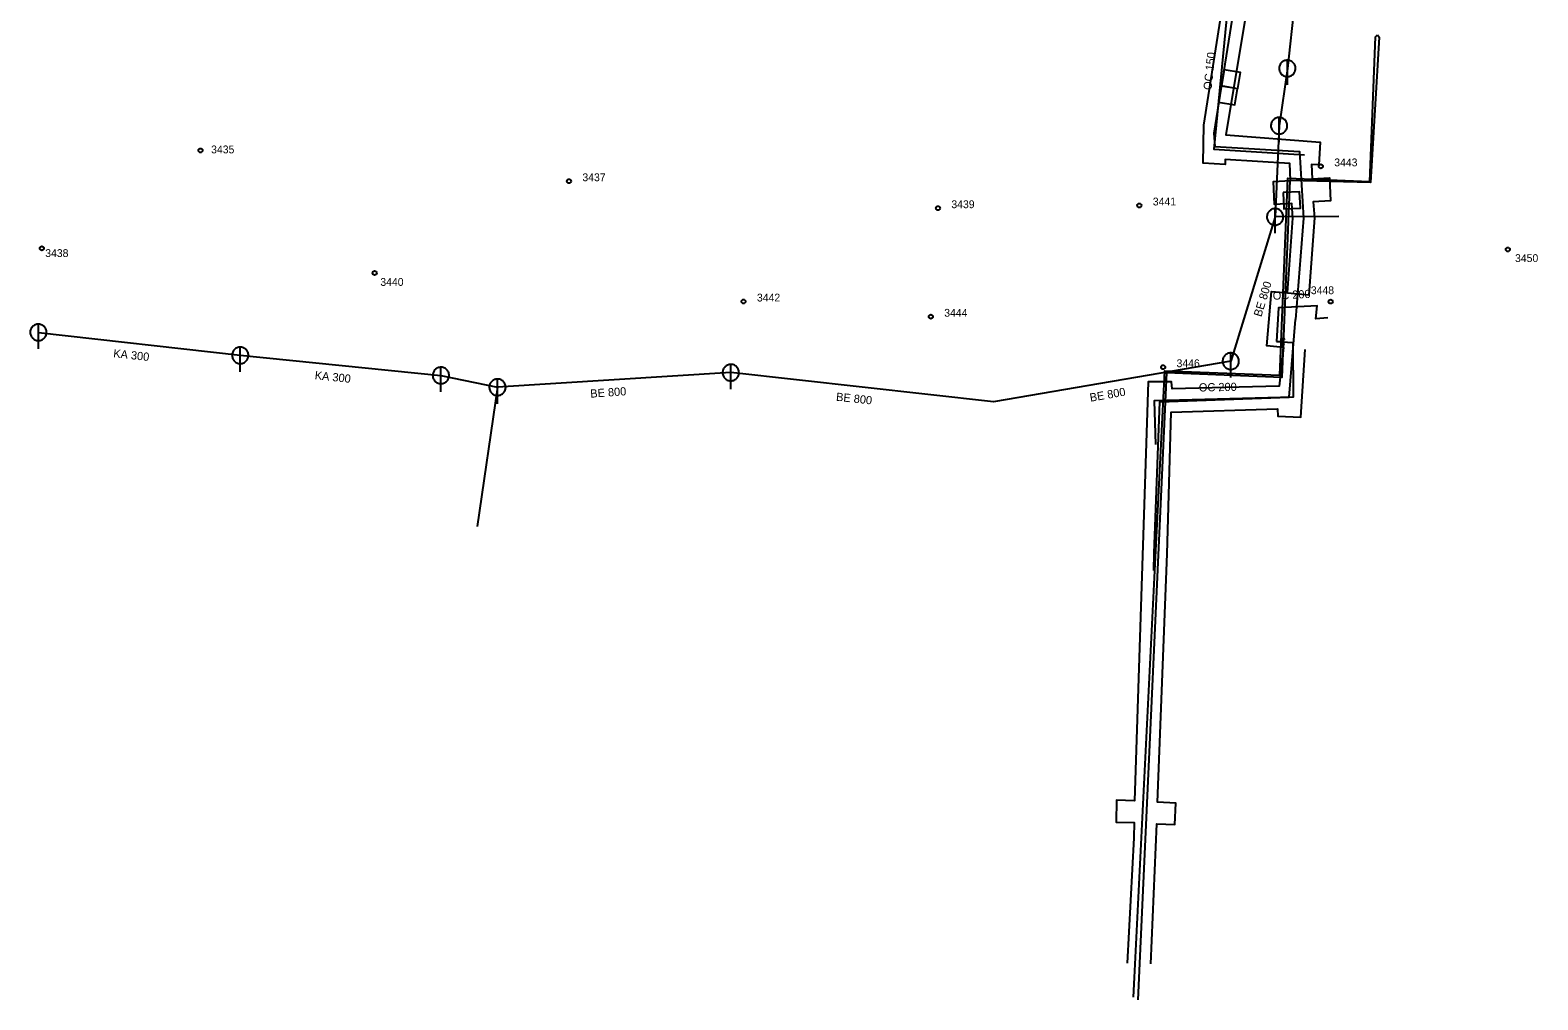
# Model space of a CAD drawing. Extents: x -759784 to -759434, y -974861 to -974639.
# Drawn here: x -759617.7 to -759434.2, y -974860.7 to -974742.8 of the extents above; entities that cross this region are included whole.
import ezdxf

# ---------------------------------------------------------------- set-up
doc = ezdxf.new("R2010")
doc.units = 0
for name, color, linetype in [('IS_CETIN_kolektor', 7, 'Continuous'), ('IS_CETIN_sdělovací kabel_podzemní', 7, 'Continuous'), ('IS_CEZ_Teplarenská_horkovod', 7, 'Continuous'), ('IS_CEZ_Teplarenská_kondenzát', 7, 'Continuous'), ('IS_DpmUL_stožáry', 7, 'Continuous'), ('IS_popis_DpmUL', 7, 'Continuous'), ('IS_popis_ScVK', 7, 'Continuous'), ('IS_ScVK_Kanal', 7, 'Continuous'), ('IS_ScVK_Vodovod', 7, 'Continuous')]:
    doc.layers.add(name, color=color, linetype=linetype)

msp = doc.modelspace()

# ---------------------------------------------------------------- linework, layer by layer
at = {"layer": 'IS_CETIN_kolektor'}
for points in [[(-759464.71, -974774.76), (-759464.04, -974765.67), (-759464.19, -974763.9), (-759466.29, -974764), (-759466.42, -974761.21), (-759464.33, -974761.1), (-759464.43, -974759.03), (-759472.28, -974758.54), (-759472.29, -974759.14), (-759474.98, -974758.97), (-759474.9, -974754.36), (-759472.4, -974738.58)], [(-759469.43, -974738.93), (-759472.22, -974755.53), (-759460.73, -974756.42), (-759460.88, -974759.18), (-759461.79, -974759.14), (-759461.7, -974760.88), (-759459.6, -974760.78), (-759459.47, -974763.57), (-759461.56, -974763.68), (-759461.4, -974765.63), (-759462.09, -974774.99)], [(-759465.2, -974781.4), (-759467.22, -974781.22), (-759466.64, -974774.59), (-759464.71, -974774.76)], [(-759464.71, -974774.76), (-759462.09, -974774.99)], [(-759465.2, -974781.4), (-759465.72, -974786.1), (-759478.75, -974786.43), (-759478.8, -974785.59), (-759481.66, -974785.6), (-759483.33, -974836.55), (-759485.53, -974836.45), (-759485.57, -974839.15), (-759483.37, -974839.19), (-759483.4, -974841.03), (-759484.22, -974856.27)], [(-759481.35, -974856.37), (-759480.62, -974839.33), (-759478.42, -974839.42), (-759478.31, -974836.81), (-759480.51, -974836.71), (-759479.35, -974806.49), (-759478.84, -974789.28), (-759465.9, -974788.85), (-759465.86, -974789.74), (-759463.08, -974789.88), (-759462.57, -974781.63)]]:
    msp.add_lwpolyline(points, dxfattribs=at)
for points in [[(-759472.39, -974747.62), (-759472.722, -974749.593), (-759470.749, -974749.924), (-759470.417, -974747.952)], [(-759472.76, -974749.6), (-759473.092, -974751.573), (-759471.119, -974751.904), (-759470.787, -974749.932)], [(-759465.23, -974762.56), (-759465.137, -974764.558), (-759463.139, -974764.465), (-759463.232, -974762.467)]]:
    msp.add_lwpolyline(points, close=True, dxfattribs=at)
at = {"layer": 'IS_CETIN_sdělovací kabel_podzemní'}
for points in [[(-759454.97, -974692.92), (-759455.48, -974700.73), (-759455.96, -974712.17), (-759466.21, -974711.58), (-759468.57, -974724.36), (-759470.97, -974738.53), (-759473.67, -974755.35), (-759473.56, -974756.95), (-759463.26, -974757.59), (-759462.76, -974765.66), (-759463.72, -974777.99)], [(-759480.98, -974808.53), (-759480.91, -974806.42), (-759480.24, -974788), (-759464.48, -974787.46), (-759463.72, -974777.99)]]:
    msp.add_lwpolyline(points, dxfattribs=at)
at = {"layer": 'IS_CEZ_Teplarenská_horkovod'}
msp.add_lwpolyline([(-759483.46, -974860.4), (-759483.34, -974858.04), (-759479.64, -974784.23), (-759465.65, -974784.79), (-759464.68, -974760.81), (-759454.69, -974761.21), (-759454, -974743.63), (-759453.75, -974743.37)], dxfattribs=at)
at = {"layer": 'IS_CEZ_Teplarenská_kondenzát'}
msp.add_lwpolyline([(-759453.75, -974743.37), (-759453.55, -974743.65), (-759454.59, -974761.34), (-759464.4, -974761.09), (-759465.39, -974785.05), (-759479.43, -974784.47), (-759482.91, -974860.74)], dxfattribs=at)
at = {"layer": 'IS_DpmUL_stožáry'}
for centre in [(-759596.978, -974757.443), (-759460.648, -974759.373), (-759552.138, -974761.183), (-759482.728, -974764.133), (-759507.238, -974764.463), (-759616.288, -974769.343), (-759437.888, -974769.483), (-759575.788, -974772.343), (-759530.898, -974775.813), (-759459.448, -974775.823), (-759508.108, -974777.663), (-759479.838, -974783.803)]:
    msp.add_circle(centre, 0.25, dxfattribs=at)
at = {"layer": 'IS_ScVK_Kanal'}
for points in [[(-759462.129, -974723.827), (-759464.723, -974747.469)], [(-759464.723, -974747.469), (-759465.724, -974754.43)], [(-759463.723, -974747.469), (-759463.728, -974747.36), (-759463.746, -974747.252), (-759463.776, -974747.146), (-759463.816, -974747.045), (-759463.868, -974746.948), (-759463.93, -974746.858), (-759464.002, -974746.775), (-759464.082, -974746.701), (-759464.17, -974746.635), (-759464.264, -974746.58), (-759464.364, -974746.535), (-759464.469, -974746.502), (-759464.576, -974746.48), (-759464.685, -974746.47), (-759464.795, -974746.472), (-759464.903, -974746.486), (-759465.01, -974746.511), (-759465.113, -974746.548), (-759465.211, -974746.597), (-759465.303, -974746.655), (-759465.389, -974746.724), (-759465.466, -974746.801), (-759465.535, -974746.887), (-759465.594, -974746.979), (-759465.642, -974747.077), (-759465.679, -974747.18), (-759465.705, -974747.287), (-759465.719, -974747.395), (-759465.722, -974747.505), (-759465.712, -974747.614), (-759465.691, -974747.721), (-759465.657, -974747.825), (-759465.613, -974747.925), (-759465.558, -974748.02), (-759465.492, -974748.108), (-759465.418, -974748.188), (-759465.335, -974748.26), (-759465.245, -974748.322), (-759465.149, -974748.374), (-759465.047, -974748.415), (-759464.942, -974748.445), (-759464.834, -974748.463), (-759464.724, -974748.469), (-759464.615, -974748.463), (-759464.507, -974748.445), (-759464.402, -974748.416), (-759464.3, -974748.375), (-759464.203, -974748.323), (-759464.113, -974748.261), (-759464.03, -974748.19), (-759463.955, -974748.11), (-759463.89, -974748.022), (-759463.834, -974747.928), (-759463.79, -974747.828), (-759463.756, -974747.724), (-759463.734, -974747.616), (-759463.724, -974747.507), (-759463.723, -974747.469)], [(-759464.723, -974749.469), (-759464.722, -974746.469)], [(-759464.724, -974754.43), (-759464.729, -974754.321), (-759464.747, -974754.213), (-759464.777, -974754.107), (-759464.817, -974754.006), (-759464.869, -974753.909), (-759464.931, -974753.819), (-759465.003, -974753.736), (-759465.083, -974753.662), (-759465.171, -974753.596), (-759465.265, -974753.541), (-759465.365, -974753.496), (-759465.47, -974753.463), (-759465.577, -974753.441), (-759465.686, -974753.431), (-759465.796, -974753.433), (-759465.904, -974753.447), (-759466.011, -974753.472), (-759466.114, -974753.509), (-759466.212, -974753.558), (-759466.304, -974753.616), (-759466.39, -974753.685), (-759466.467, -974753.762), (-759466.536, -974753.848), (-759466.595, -974753.94), (-759466.643, -974754.038), (-759466.68, -974754.141), (-759466.706, -974754.248), (-759466.72, -974754.356), (-759466.723, -974754.466), (-759466.713, -974754.575), (-759466.692, -974754.682), (-759466.658, -974754.786), (-759466.614, -974754.886), (-759466.559, -974754.981), (-759466.493, -974755.069), (-759466.419, -974755.149), (-759466.336, -974755.221), (-759466.246, -974755.283), (-759466.15, -974755.335), (-759466.048, -974755.376), (-759465.943, -974755.406), (-759465.835, -974755.424), (-759465.725, -974755.43), (-759465.616, -974755.424), (-759465.508, -974755.406), (-759465.403, -974755.377), (-759465.301, -974755.336), (-759465.204, -974755.284), (-759465.114, -974755.222), (-759465.031, -974755.151), (-759464.956, -974755.071), (-759464.891, -974754.983), (-759464.835, -974754.889), (-759464.791, -974754.789), (-759464.757, -974754.685), (-759464.735, -974754.577), (-759464.725, -974754.468), (-759464.724, -974754.43)], [(-759465.724, -974754.43), (-759466.209, -974765.517)], [(-759465.724, -974756.43), (-759465.723, -974753.43)], [(-759466.209, -974765.517), (-759471.607, -974783.071)], [(-759465.209, -974765.517), (-759465.214, -974765.408), (-759465.232, -974765.3), (-759465.262, -974765.194), (-759465.302, -974765.093), (-759465.354, -974764.996), (-759465.416, -974764.906), (-759465.488, -974764.823), (-759465.568, -974764.749), (-759465.656, -974764.683), (-759465.75, -974764.628), (-759465.85, -974764.583), (-759465.955, -974764.55), (-759466.062, -974764.528), (-759466.171, -974764.518), (-759466.281, -974764.52), (-759466.389, -974764.534), (-759466.496, -974764.559), (-759466.599, -974764.596), (-759466.697, -974764.645), (-759466.789, -974764.703), (-759466.875, -974764.772), (-759466.952, -974764.849), (-759467.021, -974764.935), (-759467.08, -974765.027), (-759467.128, -974765.125), (-759467.165, -974765.228), (-759467.191, -974765.335), (-759467.205, -974765.443), (-759467.208, -974765.553), (-759467.198, -974765.662), (-759467.177, -974765.769), (-759467.143, -974765.873), (-759467.099, -974765.973), (-759467.044, -974766.068), (-759466.978, -974766.156), (-759466.904, -974766.236), (-759466.821, -974766.308), (-759466.731, -974766.37), (-759466.635, -974766.422), (-759466.533, -974766.463), (-759466.428, -974766.493), (-759466.32, -974766.511), (-759466.21, -974766.517), (-759466.101, -974766.511), (-759465.993, -974766.493), (-759465.888, -974766.464), (-759465.786, -974766.423), (-759465.689, -974766.371), (-759465.599, -974766.309), (-759465.516, -974766.238), (-759465.441, -974766.158), (-759465.376, -974766.07), (-759465.32, -974765.976), (-759465.276, -974765.876), (-759465.242, -974765.772), (-759465.22, -974765.664), (-759465.21, -974765.555), (-759465.209, -974765.517)], [(-759466.209, -974767.517), (-759466.208, -974764.517)], [(-759458.451, -974765.485), (-759466.209, -974765.517)], [(-759615.708, -974779.566), (-759615.713, -974779.457), (-759615.731, -974779.349), (-759615.761, -974779.243), (-759615.801, -974779.142), (-759615.853, -974779.045), (-759615.915, -974778.955), (-759615.987, -974778.872), (-759616.067, -974778.798), (-759616.155, -974778.732), (-759616.249, -974778.677), (-759616.349, -974778.632), (-759616.454, -974778.599), (-759616.561, -974778.577), (-759616.67, -974778.567), (-759616.78, -974778.569), (-759616.888, -974778.583), (-759616.995, -974778.608), (-759617.098, -974778.645), (-759617.196, -974778.694), (-759617.288, -974778.752), (-759617.374, -974778.821), (-759617.451, -974778.898), (-759617.52, -974778.984), (-759617.579, -974779.076), (-759617.627, -974779.174), (-759617.664, -974779.277), (-759617.69, -974779.384), (-759617.704, -974779.492), (-759617.707, -974779.602), (-759617.697, -974779.711), (-759617.676, -974779.818), (-759617.642, -974779.922), (-759617.598, -974780.022), (-759617.543, -974780.117), (-759617.477, -974780.205), (-759617.403, -974780.285), (-759617.32, -974780.357), (-759617.23, -974780.419), (-759617.134, -974780.471), (-759617.032, -974780.512), (-759616.927, -974780.542), (-759616.819, -974780.56), (-759616.709, -974780.566), (-759616.6, -974780.56), (-759616.492, -974780.542), (-759616.387, -974780.513), (-759616.285, -974780.472), (-759616.188, -974780.42), (-759616.098, -974780.358), (-759616.015, -974780.287), (-759615.94, -974780.207), (-759615.875, -974780.119), (-759615.819, -974780.025), (-759615.775, -974779.925), (-759615.741, -974779.821), (-759615.719, -974779.713), (-759615.709, -974779.604), (-759615.708, -974779.566)], [(-759616.708, -974781.566), (-759616.707, -974778.566)], [(-759616.708, -974779.566), (-759592.136, -974782.359)], [(-759591.136, -974782.359), (-759591.141, -974782.25), (-759591.159, -974782.142), (-759591.189, -974782.036), (-759591.229, -974781.935), (-759591.281, -974781.838), (-759591.343, -974781.748), (-759591.415, -974781.665), (-759591.495, -974781.591), (-759591.583, -974781.525), (-759591.677, -974781.47), (-759591.777, -974781.425), (-759591.882, -974781.392), (-759591.989, -974781.37), (-759592.098, -974781.36), (-759592.208, -974781.362), (-759592.316, -974781.376), (-759592.423, -974781.401), (-759592.526, -974781.438), (-759592.624, -974781.487), (-759592.716, -974781.545), (-759592.802, -974781.614), (-759592.879, -974781.691), (-759592.948, -974781.777), (-759593.007, -974781.869), (-759593.055, -974781.967), (-759593.092, -974782.07), (-759593.118, -974782.177), (-759593.132, -974782.285), (-759593.135, -974782.395), (-759593.125, -974782.504), (-759593.104, -974782.611), (-759593.07, -974782.715), (-759593.026, -974782.815), (-759592.971, -974782.91), (-759592.905, -974782.998), (-759592.831, -974783.078), (-759592.748, -974783.15), (-759592.658, -974783.212), (-759592.562, -974783.264), (-759592.46, -974783.305), (-759592.355, -974783.335), (-759592.247, -974783.353), (-759592.137, -974783.359), (-759592.028, -974783.353), (-759591.92, -974783.335), (-759591.815, -974783.306), (-759591.713, -974783.265), (-759591.616, -974783.213), (-759591.526, -974783.151), (-759591.443, -974783.08), (-759591.368, -974783), (-759591.303, -974782.912), (-759591.247, -974782.818), (-759591.203, -974782.718), (-759591.169, -974782.614), (-759591.147, -974782.506), (-759591.137, -974782.397), (-759591.136, -974782.359)], [(-759592.136, -974784.359), (-759592.135, -974781.359)], [(-759592.136, -974782.359), (-759567.72, -974784.807)], [(-759470.607, -974783.071), (-759470.612, -974782.962), (-759470.63, -974782.854), (-759470.66, -974782.748), (-759470.7, -974782.647), (-759470.752, -974782.55), (-759470.814, -974782.46), (-759470.886, -974782.377), (-759470.966, -974782.303), (-759471.054, -974782.237), (-759471.148, -974782.182), (-759471.248, -974782.137), (-759471.353, -974782.104), (-759471.46, -974782.082), (-759471.569, -974782.072), (-759471.679, -974782.074), (-759471.787, -974782.088), (-759471.894, -974782.113), (-759471.997, -974782.15), (-759472.095, -974782.199), (-759472.187, -974782.257), (-759472.273, -974782.326), (-759472.35, -974782.403), (-759472.419, -974782.489), (-759472.478, -974782.581), (-759472.526, -974782.679), (-759472.563, -974782.782), (-759472.589, -974782.889), (-759472.603, -974782.997), (-759472.606, -974783.107), (-759472.596, -974783.216), (-759472.575, -974783.323), (-759472.541, -974783.427), (-759472.497, -974783.527), (-759472.442, -974783.622), (-759472.376, -974783.71), (-759472.302, -974783.79), (-759472.219, -974783.862), (-759472.129, -974783.924), (-759472.033, -974783.976), (-759471.931, -974784.017), (-759471.826, -974784.047), (-759471.718, -974784.065), (-759471.608, -974784.071), (-759471.499, -974784.065), (-759471.391, -974784.047), (-759471.286, -974784.018), (-759471.184, -974783.977), (-759471.087, -974783.925), (-759470.997, -974783.863), (-759470.914, -974783.792), (-759470.839, -974783.712), (-759470.774, -974783.624), (-759470.718, -974783.53), (-759470.674, -974783.43), (-759470.64, -974783.326), (-759470.618, -974783.218), (-759470.608, -974783.109), (-759470.607, -974783.071)], [(-759471.607, -974785.071), (-759471.606, -974782.071)], [(-759566.72, -974784.807), (-759566.725, -974784.698), (-759566.743, -974784.59), (-759566.773, -974784.484), (-759566.813, -974784.383), (-759566.865, -974784.286), (-759566.927, -974784.196), (-759566.999, -974784.113), (-759567.079, -974784.039), (-759567.167, -974783.973), (-759567.261, -974783.918), (-759567.361, -974783.873), (-759567.466, -974783.84), (-759567.573, -974783.818), (-759567.682, -974783.808), (-759567.792, -974783.81), (-759567.9, -974783.824), (-759568.007, -974783.849), (-759568.11, -974783.886), (-759568.208, -974783.935), (-759568.3, -974783.993), (-759568.386, -974784.062), (-759568.463, -974784.139), (-759568.532, -974784.225), (-759568.591, -974784.317), (-759568.639, -974784.415), (-759568.676, -974784.518), (-759568.702, -974784.625), (-759568.716, -974784.733), (-759568.719, -974784.843), (-759568.709, -974784.952), (-759568.688, -974785.059), (-759568.654, -974785.163), (-759568.61, -974785.263), (-759568.555, -974785.358), (-759568.489, -974785.446), (-759568.415, -974785.526), (-759568.332, -974785.598), (-759568.242, -974785.66), (-759568.146, -974785.712), (-759568.044, -974785.753), (-759567.939, -974785.783), (-759567.831, -974785.801), (-759567.721, -974785.807), (-759567.612, -974785.801), (-759567.504, -974785.783), (-759567.399, -974785.754), (-759567.297, -974785.713), (-759567.2, -974785.661), (-759567.11, -974785.599), (-759567.027, -974785.528), (-759566.952, -974785.448), (-759566.887, -974785.36), (-759566.831, -974785.266), (-759566.787, -974785.166), (-759566.753, -974785.062), (-759566.731, -974784.954), (-759566.721, -974784.845), (-759566.72, -974784.807)], [(-759567.72, -974786.807), (-759567.719, -974783.807)], [(-759531.449, -974784.457), (-759531.454, -974784.348), (-759531.472, -974784.24), (-759531.502, -974784.134), (-759531.542, -974784.033), (-759531.594, -974783.936), (-759531.656, -974783.846), (-759531.728, -974783.763), (-759531.808, -974783.689), (-759531.896, -974783.623), (-759531.99, -974783.568), (-759532.09, -974783.523), (-759532.195, -974783.49), (-759532.302, -974783.468), (-759532.411, -974783.458), (-759532.521, -974783.46), (-759532.629, -974783.474), (-759532.736, -974783.499), (-759532.839, -974783.536), (-759532.937, -974783.585), (-759533.029, -974783.643), (-759533.115, -974783.712), (-759533.192, -974783.789), (-759533.261, -974783.875), (-759533.32, -974783.967), (-759533.368, -974784.065), (-759533.405, -974784.168), (-759533.431, -974784.275), (-759533.445, -974784.383), (-759533.448, -974784.493), (-759533.438, -974784.602), (-759533.417, -974784.709), (-759533.383, -974784.813), (-759533.339, -974784.913), (-759533.284, -974785.008), (-759533.218, -974785.096), (-759533.144, -974785.176), (-759533.061, -974785.248), (-759532.971, -974785.31), (-759532.875, -974785.362), (-759532.773, -974785.403), (-759532.668, -974785.433), (-759532.56, -974785.451), (-759532.45, -974785.457), (-759532.341, -974785.451), (-759532.233, -974785.433), (-759532.128, -974785.404), (-759532.026, -974785.363), (-759531.929, -974785.311), (-759531.839, -974785.249), (-759531.756, -974785.178), (-759531.681, -974785.098), (-759531.616, -974785.01), (-759531.56, -974784.916), (-759531.516, -974784.816), (-759531.482, -974784.712), (-759531.46, -974784.604), (-759531.45, -974784.495), (-759531.449, -974784.457)], [(-759532.449, -974786.457), (-759532.448, -974783.457)], [(-759471.607, -974783.071), (-759500.496, -974788.02)], [(-759567.72, -974784.807), (-759560.839, -974786.239)], [(-759559.839, -974786.239), (-759559.844, -974786.13), (-759559.862, -974786.022), (-759559.892, -974785.916), (-759559.932, -974785.815), (-759559.984, -974785.718), (-759560.046, -974785.628), (-759560.118, -974785.545), (-759560.198, -974785.471), (-759560.286, -974785.405), (-759560.38, -974785.35), (-759560.48, -974785.305), (-759560.585, -974785.272), (-759560.692, -974785.25), (-759560.801, -974785.24), (-759560.911, -974785.242), (-759561.019, -974785.256), (-759561.126, -974785.281), (-759561.229, -974785.318), (-759561.327, -974785.367), (-759561.419, -974785.425), (-759561.505, -974785.494), (-759561.582, -974785.571), (-759561.651, -974785.657), (-759561.71, -974785.749), (-759561.758, -974785.847), (-759561.795, -974785.95), (-759561.821, -974786.057), (-759561.835, -974786.165), (-759561.838, -974786.275), (-759561.828, -974786.384), (-759561.807, -974786.491), (-759561.773, -974786.595), (-759561.729, -974786.695), (-759561.674, -974786.79), (-759561.608, -974786.878), (-759561.534, -974786.958), (-759561.451, -974787.03), (-759561.361, -974787.092), (-759561.265, -974787.144), (-759561.163, -974787.185), (-759561.058, -974787.215), (-759560.95, -974787.233), (-759560.84, -974787.239), (-759560.731, -974787.233), (-759560.623, -974787.215), (-759560.518, -974787.186), (-759560.416, -974787.145), (-759560.319, -974787.093), (-759560.229, -974787.031), (-759560.146, -974786.96), (-759560.071, -974786.88), (-759560.006, -974786.792), (-759559.95, -974786.698), (-759559.906, -974786.598), (-759559.872, -974786.494), (-759559.85, -974786.386), (-759559.84, -974786.277), (-759559.839, -974786.239)], [(-759532.449, -974784.457), (-759560.839, -974786.239)], [(-759560.839, -974788.239), (-759560.838, -974785.239)], [(-759500.496, -974788.02), (-759532.449, -974784.457)], [(-759560.839, -974786.239), (-759563.295, -974803.166)]]:
    msp.add_lwpolyline(points, dxfattribs=at)
at = {"layer": 'IS_ScVK_Vodovod'}
for points in [[(-759471.711, -974737.208), (-759473.653, -974757.27), (-759462.636, -974757.977)], [(-759459.778, -974777.781), (-759461.258, -974777.905), (-759461.074, -974776.337), (-759465.784, -974776.57), (-759466.035, -974780.678)], [(-759466.035, -974780.678), (-759464.057, -974780.802), (-759463.998, -974787.464), (-759480.914, -974787.885), (-759480.779, -974793.201)], [(-759465.236, -974780.726), (-759466.034, -974780.678)], [(-759465.388, -974780.467), (-759465.205, -974780.231)], [(-759465.058, -974780.491), (-759465.388, -974780.467)], [(-759465.072, -974780.466), (-759465.371, -974780.445)], [(-759465.086, -974780.438), (-759465.353, -974780.419)], [(-759465.104, -974780.413), (-759465.331, -974780.396)], [(-759465.118, -974780.387), (-759465.314, -974780.373)], [(-759465.132, -974780.363), (-759465.298, -974780.351)], [(-759465.145, -974780.334), (-759465.279, -974780.325)], [(-759465.266, -974781.222), (-759465.205, -974780.231)], [(-759465.16, -974780.31), (-759465.262, -974780.303)], [(-759465.177, -974780.285), (-759465.24, -974780.28)], [(-759465.191, -974780.255), (-759465.223, -974780.253)], [(-759465.205, -974780.231), (-759465.058, -974780.491)], [(-759465.088, -974780.982), (-759465.418, -974780.966)], [(-759465.418, -974780.966), (-759465.266, -974781.222)], [(-759465.105, -974781.005), (-759465.404, -974780.99)], [(-759465.122, -974781.031), (-759465.39, -974781.018)], [(-759465.143, -974781.054), (-759465.371, -974781.043)], [(-759465.16, -974781.078), (-759465.357, -974781.068)], [(-759465.177, -974781.1), (-759465.343, -974781.092)], [(-759465.194, -974781.127), (-759465.328, -974781.12)], [(-759465.211, -974781.149), (-759465.313, -974781.144)], [(-759465.232, -974781.172), (-759465.295, -974781.169)], [(-759465.248, -974781.2), (-759465.28, -974781.198)], [(-759465.266, -974781.222), (-759465.088, -974780.982)]]:
    msp.add_lwpolyline(points, dxfattribs=at)

# ---------------------------------------------------------------- texts
at = {"layer": 'IS_popis_DpmUL'}
for s, p in [('3435', (-759595.685, -974757.792)), ('3443', (-759459.015, -974759.372)), ('3437', (-759550.505, -974761.182)), ('3439', (-759505.605, -974764.462)), ('3441', (-759481.095, -974764.132)), ('3438', (-759615.875, -974770.402)), ('3450', (-759437.015, -974771.012)), ('3440', (-759575.095, -974773.912)), ('3442', (-759529.265, -974775.812)), ('3448', (-759461.865, -974774.922)), ('3444', (-759506.475, -974777.662)), ('3446', (-759478.205, -974783.802))]:
    msp.add_text(s, height=0.95, dxfattribs=at).set_placement(p)
at = {"layer": 'IS_popis_ScVK'}
for s, rotation, p in [('OC 150', 84, (-759473.952, -974750.13)), ('BE 800', 73, (-759467.892, -974777.745)), ('OC 200', 3, (-759466.473, -974775.617)), ('KA 300', 354, (-759607.627, -974782.597)), ('KA 300', 354, (-759583.11, -974785.259)), ('BE 800', 4, (-759549.513, -974787.516)), ('OC 200', 1, (-759475.479, -974786.763)), ('BE 800', 354, (-759519.673, -974787.879)), ('BE 800', 10, (-759488.673, -974788.008))]:
    msp.add_text(s, height=1, rotation=rotation, dxfattribs=at).set_placement(p)

doc.saveas('drawing.dxf')
